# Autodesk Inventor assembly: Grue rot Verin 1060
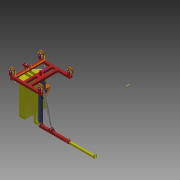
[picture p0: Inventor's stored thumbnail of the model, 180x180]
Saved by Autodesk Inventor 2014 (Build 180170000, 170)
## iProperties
Created: 2015-07
Part Number: Grue rot Verin 1060
Document SubType Name: Assembly
Designer: OL
Author: OL
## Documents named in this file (29)
- D:\Lycée Larmand\Profs\SUJET BAC EDPI ETC\ELABORATION SUJET EDPI\Bourgeois RT 510\Modele Grue rotative\Grue rot Verin 1060.iam
- D:\Lycée Larmand\Profs\SUJET BAC EDPI ETC\ELABORATION SUJET EDPI\Bourgeois RT 510\Modele Grue rotative\Cadre chariot.ipt
- D:\Lycée Larmand\Profs\SUJET BAC EDPI ETC\ELABORATION SUJET EDPI\Bourgeois RT 510\Modele Grue rotative\Axe.ipt
- D:\Lycée Larmand\Profs\SUJET BAC EDPI ETC\ELABORATION SUJET EDPI\Bourgeois RT 510\Modele Grue rotative\Poteau central.ipt
- D:\Lycée Larmand\Profs\SUJET BAC EDPI ETC\ELABORATION SUJET EDPI\Bourgeois RT 510\Modele Grue rotative\Potence pivot.ipt
- D:\Lycée Larmand\Profs\SUJET BAC EDPI ETC\ELABORATION SUJET EDPI\Bourgeois RT 510\Modele Grue rotative\Potence coulissante.ipt
- D:\Lycée Larmand\Profs\SUJET BAC EDPI ETC\ELABORATION SUJET EDPI\Bourgeois RT 510\Modele Grue rotative\Contrepoids.ipt
- D:\Lycée Larmand\Profs\SUJET BAC EDPI ETC\ELABORATION SUJET EDPI\Bourgeois RT 510\Modele Grue rotative\pompe\Pompe.ipt
- D:\Lycée Larmand\Profs\SUJET BAC EDPI ETC\ELABORATION SUJET EDPI\Bourgeois RT 510\Modele Grue rotative\Verin630-5-corps.ipt
- D:\Lycée Larmand\Profs\SUJET BAC EDPI ETC\ELABORATION SUJET EDPI\Bourgeois RT 510\Modele Grue rotative\Verin630-5-tige.ipt
- D:\Lycée Larmand\Profs\SUJET BAC EDPI ETC\ELABORATION SUJET EDPI\Bourgeois RT 510\Modele Grue rotative\Roue.ipt
- D:\Lycée Larmand\Profs\SUJET BAC EDPI ETC\ELABORATION SUJET EDPI\Bourgeois RT 510\Modele Grue rotative\Pivot de Direction.ipt
- D:\Lycée Larmand\Profs\SUJET BAC EDPI ETC\ELABORATION SUJET EDPI\Bourgeois RT 510\Modele Grue rotative\Palier de roue.ipt
- D:\Lycée Larmand\Profs\SUJET BAC EDPI ETC\ELABORATION SUJET EDPI\Bourgeois RT 510\Modele Grue rotative\Biellette.ipt
- D:\Lycée Larmand\Profs\SUJET BAC EDPI ETC\ELABORATION SUJET EDPI\Bourgeois RT 510\Modele Grue rotative\Vis H M10x20_02.ipt
- D:\Lycée Larmand\Profs\SUJET BAC EDPI ETC\ELABORATION SUJET EDPI\Bourgeois RT 510\Modele Grue rotative\Ecrou H M10x20_01.ipt
- D:\Lycée Larmand\Profs\SUJET BAC EDPI ETC\ELABORATION SUJET EDPI\Bourgeois RT 510\Modele Grue rotative\Axe D20.ipt
- D:\Lycée Larmand\Profs\SUJET BAC EDPI ETC\ELABORATION SUJET EDPI\Bourgeois RT 510\Modele Grue rotative\Goupille D20.ipt
- D:\Lycée Larmand\Profs\SUJET BAC EDPI ETC\ELABORATION SUJET EDPI\Bourgeois RT 510\Modele Grue rotative\Axe D20 L122.ipt
- D:\Lycée Larmand\Profs\SUJET BAC EDPI ETC\ELABORATION SUJET EDPI\Bourgeois RT 510\Modele Grue rotative\Rondelle d'appui D20.ipt
- D:\Lycée Larmand\Profs\SUJET BAC EDPI ETC\ELABORATION SUJET EDPI\Bourgeois RT 510\Modele Grue rotative\Axe D20 L96.ipt
- D:\Lycée Larmand\Profs\SUJET BAC EDPI ETC\ELABORATION SUJET EDPI\Bourgeois RT 510\Modele Grue rotative\Axe Roue D25 L116.ipt
- D:\Lycée Larmand\Profs\SUJET BAC EDPI ETC\ELABORATION SUJET EDPI\Bourgeois RT 510\Modele Grue rotative\Rondelle d'appui D25.ipt
- D:\Lycée Larmand\Profs\SUJET BAC EDPI ETC\ELABORATION SUJET EDPI\Bourgeois RT 510\Modele Grue rotative\Goupille D25.ipt
- D:\Lycée Larmand\Profs\SUJET BAC EDPI ETC\ELABORATION SUJET EDPI\Bourgeois RT 510\Modele Grue rotative\Butée manuelle.ipt
- D:\Lycée Larmand\Profs\SUJET BAC EDPI ETC\ELABORATION SUJET EDPI\Bourgeois RT 510\Modele Grue rotative\Goupille Cavalier.ipt
- D:\Lycée Larmand\Profs\SUJET BAC EDPI ETC\ELABORATION SUJET EDPI\Bourgeois RT 510\Modele Grue rotative\Bague d'arrêt D25.ipt
- D:\Lycée Larmand\Profs\SUJET BAC EDPI ETC\ELABORATION SUJET EDPI\Bourgeois RT 510\Modele Grue rotative\tuyau 1.ipt
- D:\Lycée Larmand\Profs\SUJET BAC EDPI ETC\ELABORATION SUJET EDPI\Bourgeois RT 510\Modele Grue rotative\tuyau 2.ipt
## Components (72 placed, 28 different names)
1. Cadre chariot:1 — Logement:1, Logement:9, Logement:10, Logement:12, Logement:13, Angle:1, Logement:37, Angle:12, Logement:38, Logement:39, Logement:42, Angle:15, Logement:43, Logement:44, Angle:16, Angle:17, Logement:54, Logement:74, Logement:75
2. Axe:1 — Logement:1, Logement:2
3. Poteau central:1 — Logement:2, Logement:3, Logement:4, Placage:3, Logement:5, Logement:6, Logement:7, Logement:21, Logement:22, Angle:3, Angle:6, Angle:7, Logement:27, Logement:28, Logement:57, Angle:20, Angle:22, Logement:58, Logement:60, Angle:24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
4. Potence pivot:1 — Logement:3, Placage:1, Placage:2, Placage:11, Logement:32, Angle:9, Logement:33, Logement:34, Logement:62, Angle:28
5. Potence coulissante:1 — Placage:1, Placage:2, Tangente:3
6. Contrepoids:1 — Logement:4, Placage:3, Angle:1, Angle:2, Logement:25, Logement:30, Logement:31
7. Pompe:1 — Logement:5, Logement:6, Logement:20, Logement:56, Angle:21, Angle:23, Logement:59, Logement:61, Angle:26, Angle:27, Logement:72
8. Verin630-5-corps:1 — Logement:7, Placage:4, Logement:73
9. Verin630-5-tige:1 — Placage:4, Placage:10
10. Roue:1 — Logement:9
11. Roue:2 — Logement:10
12. Pivot de Direction:1 — Logement:54, Logement:63, Angle:30, Angle:31, Placage:19, Placage:20
13. Palier de roue:1 — Logement:12, Logement:17, Logement:18, Placage:6, Angle:19, Logement:49, Logement:50, Logement:53, Placage:17, Angle:33
14. Palier de roue:2 — Logement:13, Logement:19, Angle:2, Placage:5, Logement:47, Angle:18, Logement:51, Logement:52, Logement:55, Placage:18, Angle:32
15. Biellette:1 — Logement:17, Placage:14, Logement:64, Logement:70
16. Biellette:2 — Logement:55, Placage:13, Logement:65, Logement:68
17. Roue:3 — Logement:18
18. Roue:4 — Logement:19
19. Vis H M10x20_02:1 — Logement:20, Angle:23
20. Ecrou H M10x20_01:1 — Logement:21, Angle:22
21. Axe D20:1 — Logement:22, Angle:3, Logement:23, Angle:4, Logement:24, Angle:5, Placage:24
22. Goupille D20:1 — Logement:24, Angle:5
23. Goupille D20:2 — Logement:23, Angle:4
24. Goupille D20:3 — Logement:26, Angle:7
25. Goupille D20:4 — Logement:29, Angle:8
26. Axe D20 L122:1 — Logement:25, Logement:26, Angle:6, Logement:29, Angle:8
27. Rondelle d'appui D20:1 — Logement:27
28. Rondelle d'appui D20:2 — Logement:28
29. Rondelle d'appui D20:3 — Logement:30
30. Rondelle d'appui D20:4 — Logement:31
31. Axe D20 L96:1 — Logement:32, Angle:9, Logement:35, Angle:10, Logement:36, Angle:11, Placage:23
32. Rondelle d'appui D20:5 — Logement:34
33. Rondelle d'appui D20:6 — Logement:33
34. Goupille D20:5 — Logement:35, Angle:10
35. Goupille D20:6 — Logement:36, Angle:11
36. Axe Roue D25 L116:1 — Logement:37, Angle:12, Angle:13, Angle:14
37. Rondelle d'appui D25:1 — Logement:38, Logement:41
38. Rondelle d'appui D25:2 — Logement:39, Logement:40
39. Goupille D25:1 — Logement:41, Angle:14
40. Goupille D25:2 — Logement:40, Angle:13
41. Axe Roue D25 L116:2 — Logement:42, Angle:15
42. Rondelle d'appui D25:3 — Logement:44, Logement:45
43. Rondelle d'appui D25:4 — Logement:43, Logement:46
44. Goupille D25:3 — Logement:45, Angle:16
45. Goupille D25:4 — Logement:46, Angle:17
46. Axe Roue D25 L116:3 — Logement:47, Angle:18
47. Axe Roue D25 L116:4 — Angle:19, Logement:53
48. Rondelle d'appui D25:5 — Logement:49
49. Rondelle d'appui D25:6 — Logement:50
50. Rondelle d'appui D25:7 — Logement:52
51. Rondelle d'appui D25:8 — Logement:51
52. Vis H M10x20_02:2 — Logement:56, Angle:21
53. Ecrou H M10x20_01:2 — Logement:57, Angle:20
54. Vis H M10x20_02:3 — Logement:59, Angle:26
55. Ecrou H M10x20_01:3 — Logement:58, Angle:24
56. Vis H M10x20_02:4 — Logement:61, Angle:27
57. Ecrou H M10x20_01:4 — Logement:60, Angle:25
58. Butée manuelle:1 — Logement:62, Angle:28, Placage:15, Affleurement:1, Angle:29, Tangente:3
59. Goupille Cavalier:1 — Placage:16, Affleurement:1, Angle:29
60. Bague d'arrêt D25:1 — Logement:63
61. Rondelle d'appui D20:7 — Logement:65, Logement:66, Placage:22
62. Rondelle d'appui D20:8 — Logement:64, Logement:67
63. Goupille D20:7 — Logement:66, Angle:30
64. Goupille D20:8 — Logement:67, Angle:31
65. Goupille D20:9 — Logement:69, Angle:32
66. Rondelle d'appui D20:9 — Logement:68, Logement:69
67. Rondelle d'appui D20:10 — Logement:70, Logement:71
68. Goupille D20:10 — Logement:71, Angle:33
69. tuyau 1:1 — Logement:72, Tangente:2
70. tuyau 2:1 — Logement:73, Tangente:2
71. Bague d'arrêt D25:2 — Logement:74
72. Bague d'arrêt D25:3 — Logement:75
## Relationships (124: Insert 69, Angle 33, Mate 19, Tangent 2, Flush 1)
- Logement:1 [Insert]: Cadre chariot:1 ↔ Axe:1
- Logement:2 [Insert]: Axe:1 ↔ Poteau central:1
- Logement:3 [Insert]: Poteau central:1 ↔ Potence pivot:1
- Placage:1 [Mate]: Potence pivot:1 ↔ Potence coulissante:1
- Placage:2 [Mate]: Potence pivot:1 ↔ Potence coulissante:1
- Logement:4 [Insert]: Poteau central:1 ↔ Contrepoids:1
- Placage:3 [Mate]: Poteau central:1 ↔ Contrepoids:1
- Logement:5 [Insert]: Poteau central:1 ↔ Pompe:1
- Logement:6 [Insert]: Poteau central:1 ↔ Pompe:1
- Logement:7 [Insert]: Poteau central:1 ↔ Verin630-5-corps:1
- Placage:4 [Mate]: Verin630-5-corps:1 ↔ Verin630-5-tige:1
- Logement:9 [Insert]: Cadre chariot:1 ↔ Roue:1
- Logement:10 [Insert]: Cadre chariot:1 ↔ Roue:2
- Logement:12 [Insert]: Cadre chariot:1 ↔ Palier de roue:1
- Logement:13 [Insert]: Cadre chariot:1 ↔ Palier de roue:2
- Logement:17 [Insert]: Palier de roue:1 ↔ Biellette:1
- Logement:18 [Insert]: Palier de roue:1 ↔ Roue:3
- Logement:19 [Insert]: Palier de roue:2 ↔ Roue:4
- Angle:1: Cadre chariot:1 ↔ Contrepoids:1
- Angle:2: Contrepoids:1 ↔ Palier de roue:2
- Placage:5 [Mate]: Palier de roue:2
- Placage:6 [Mate]: Palier de roue:1
- Logement:20 [Insert]: Pompe:1 ↔ Vis H M10x20_02:1
- Logement:21 [Insert]: Poteau central:1 ↔ Ecrou H M10x20_01:1
- Logement:22 [Insert]: Poteau central:1 ↔ Axe D20:1
- Angle:3: Poteau central:1 ↔ Axe D20:1
- Logement:23 [Insert]: Axe D20:1 ↔ Goupille D20:2
- Angle:4: Axe D20:1 ↔ Goupille D20:2
- Logement:24 [Insert]: Axe D20:1 ↔ Goupille D20:1
- Angle:5: Axe D20:1 ↔ Goupille D20:1
- Placage:10 [Mate]: Verin630-5-tige:1
- Placage:11 [Mate]: Potence pivot:1
- Logement:25 [Insert]: Contrepoids:1 ↔ Axe D20 L122:1
- Logement:26 [Insert]: Goupille D20:3 ↔ Axe D20 L122:1
- Angle:6: Poteau central:1 ↔ Axe D20 L122:1
- Angle:7: Poteau central:1 ↔ Goupille D20:3
- Logement:27 [Insert]: Poteau central:1 ↔ Rondelle d'appui D20:1
- Logement:28 [Insert]: Poteau central:1 ↔ Rondelle d'appui D20:2
- Logement:29 [Insert]: Goupille D20:4 ↔ Axe D20 L122:1
- Angle:8: Goupille D20:4 ↔ Axe D20 L122:1
- Logement:30 [Insert]: Contrepoids:1 ↔ Rondelle d'appui D20:3
- Logement:31 [Insert]: Contrepoids:1 ↔ Rondelle d'appui D20:4
- Logement:32 [Insert]: Potence pivot:1 ↔ Axe D20 L96:1
- Angle:9: Potence pivot:1 ↔ Axe D20 L96:1
- Logement:33 [Insert]: Potence pivot:1 ↔ Rondelle d'appui D20:6
- Logement:34 [Insert]: Potence pivot:1 ↔ Rondelle d'appui D20:5
- Logement:35 [Insert]: Axe D20 L96:1 ↔ Goupille D20:5
- Angle:10: Axe D20 L96:1 ↔ Goupille D20:5
- Logement:36 [Insert]: Axe D20 L96:1 ↔ Goupille D20:6
- Angle:11: Axe D20 L96:1 ↔ Goupille D20:6
- Logement:37 [Insert]: Cadre chariot:1 ↔ Axe Roue D25 L116:1
- Angle:12: Cadre chariot:1 ↔ Axe Roue D25 L116:1
- Logement:38 [Insert]: Cadre chariot:1 ↔ Rondelle d'appui D25:1
- Logement:39 [Insert]: Cadre chariot:1 ↔ Rondelle d'appui D25:2
- Logement:40 [Insert]: Rondelle d'appui D25:2 ↔ Goupille D25:2
- Angle:13: Axe Roue D25 L116:1 ↔ Goupille D25:2
- Logement:41 [Insert]: Rondelle d'appui D25:1 ↔ Goupille D25:1
- Angle:14: Axe Roue D25 L116:1 ↔ Goupille D25:1
- Logement:42 [Insert]: Cadre chariot:1 ↔ Axe Roue D25 L116:2
- Angle:15: Cadre chariot:1 ↔ Axe Roue D25 L116:2
- Logement:43 [Insert]: Cadre chariot:1 ↔ Rondelle d'appui D25:4
- Logement:44 [Insert]: Cadre chariot:1 ↔ Rondelle d'appui D25:3
- Logement:45 [Insert]: Rondelle d'appui D25:3 ↔ Goupille D25:3
- Angle:16: Cadre chariot:1 ↔ Goupille D25:3
- Logement:46 [Insert]: Rondelle d'appui D25:4 ↔ Goupille D25:4
- Angle:17: Cadre chariot:1 ↔ Goupille D25:4
- Logement:47 [Insert]: Palier de roue:2 ↔ Axe Roue D25 L116:3
- Angle:18: Palier de roue:2 ↔ Axe Roue D25 L116:3
- Angle:19: Palier de roue:1 ↔ Axe Roue D25 L116:4
- Logement:49 [Insert]: Palier de roue:1 ↔ Rondelle d'appui D25:5
- Logement:50 [Insert]: Palier de roue:1 ↔ Rondelle d'appui D25:6
- Logement:51 [Insert]: Palier de roue:2 ↔ Rondelle d'appui D25:8
- Logement:52 [Insert]: Palier de roue:2 ↔ Rondelle d'appui D25:7
- Logement:53 [Insert]: Palier de roue:1 ↔ Axe Roue D25 L116:4
- Logement:54 [Insert]: Cadre chariot:1 ↔ Pivot de Direction:1
- Logement:55 [Insert]: Palier de roue:2 ↔ Biellette:2
- Placage:13 [Mate]: Biellette:2
- Placage:14 [Mate]: Biellette:1
- Logement:56 [Insert]: Pompe:1 ↔ Vis H M10x20_02:2
- Logement:57 [Insert]: Poteau central:1 ↔ Ecrou H M10x20_01:2
- Angle:20: Poteau central:1 ↔ Ecrou H M10x20_01:2
- Angle:21: Pompe:1 ↔ Vis H M10x20_02:2
- Angle:22: Poteau central:1 ↔ Ecrou H M10x20_01:1
- Angle:23: Pompe:1 ↔ Vis H M10x20_02:1
- Logement:58 [Insert]: Poteau central:1 ↔ Ecrou H M10x20_01:3
- Logement:59 [Insert]: Pompe:1 ↔ Vis H M10x20_02:3
- Logement:60 [Insert]: Poteau central:1 ↔ Ecrou H M10x20_01:4
- Logement:61 [Insert]: Pompe:1 ↔ Vis H M10x20_02:4
- Angle:24: Poteau central:1 ↔ Ecrou H M10x20_01:3
- Angle:25: Poteau central:1 ↔ Ecrou H M10x20_01:4
- Angle:26: Pompe:1 ↔ Vis H M10x20_02:3
- Angle:27: Pompe:1 ↔ Vis H M10x20_02:4
- Logement:62 [Insert]: Potence pivot:1 ↔ Butée manuelle:1
- Angle:28: Potence pivot:1 ↔ Butée manuelle:1
- Placage:15 [Mate]: Butée manuelle:1
- Placage:16 [Mate]: Goupille Cavalier:1
- Affleurement:1 [Flush]: Butée manuelle:1 ↔ Goupille Cavalier:1
- Angle:29: Butée manuelle:1 ↔ Goupille Cavalier:1
- Logement:63 [Insert]: Pivot de Direction:1 ↔ Bague d'arrêt D25:1
- Logement:64 [Insert]: Biellette:1 ↔ Rondelle d'appui D20:8
- Logement:65 [Insert]: Biellette:2 ↔ Rondelle d'appui D20:7
- Logement:66 [Insert]: Rondelle d'appui D20:7 ↔ Goupille D20:7
- Angle:30: Pivot de Direction:1 ↔ Goupille D20:7
- Logement:67 [Insert]: Rondelle d'appui D20:8 ↔ Goupille D20:8
- Angle:31: Pivot de Direction:1 ↔ Goupille D20:8
- Placage:17 [Mate]: Palier de roue:1
- Placage:18 [Mate]: Palier de roue:2
- Placage:19 [Mate]: Pivot de Direction:1
- Placage:20 [Mate]: Pivot de Direction:1
- Placage:22 [Mate]: Rondelle d'appui D20:7
- Logement:68 [Insert]: Biellette:2 ↔ Rondelle d'appui D20:9
- Logement:69 [Insert]: Goupille D20:9 ↔ Rondelle d'appui D20:9
- Angle:32: Palier de roue:2 ↔ Goupille D20:9
- Logement:70 [Insert]: Biellette:1 ↔ Rondelle d'appui D20:10
- Logement:71 [Insert]: Rondelle d'appui D20:10 ↔ Goupille D20:10
- Angle:33: Palier de roue:1 ↔ Goupille D20:10
- Logement:72 [Insert]: Pompe:1 ↔ tuyau 1:1
- Logement:73 [Insert]: Verin630-5-corps:1 ↔ tuyau 2:1
- Tangente:2: tuyau 1:1 ↔ tuyau 2:1
- Logement:74 [Insert]: Cadre chariot:1 ↔ Bague d'arrêt D25:2
- Logement:75 [Insert]: Cadre chariot:1 ↔ Bague d'arrêt D25:3
- Placage:23 [Mate]: Axe D20 L96:1
- Placage:24 [Mate]: Axe D20:1
- Tangente:3: Potence coulissante:1 ↔ Butée manuelle:1
